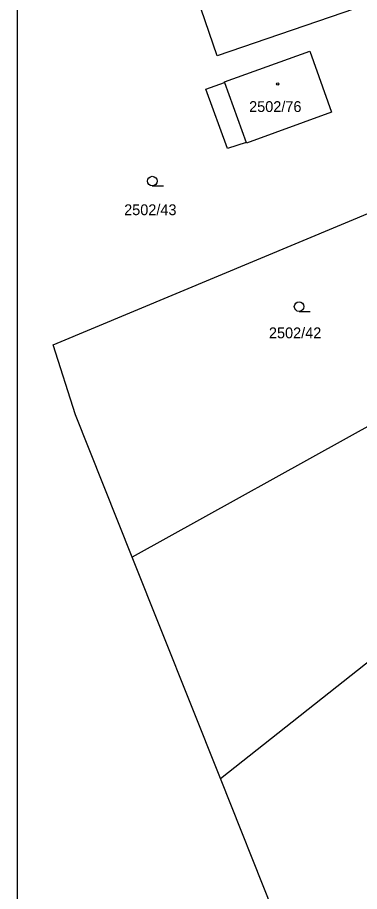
# Model space of a CAD drawing. Extents: x -558358 to -557517, y -1073786 to -1073189.
# Drawn here: x -558357.5 to -558303.9, y -1073559.5 to -1073422.1 of the extents above; entities that cross this region are included whole.
import ezdxf

# ---------------------------------------------------------------- set-up
doc = ezdxf.new("R2010")
doc.units = 0
for name, color, linetype in [('Hranice parcel', 7, 'Continuous'), ('Parcelní čísla', 7, 'Continuous'), ('Vnitřní kresba', 7, 'Continuous'), ('Vrstva 1', 7, 'Continuous'), ('Značky budov', 7, 'Continuous'), ('Značky kultur', 7, 'Continuous')]:
    doc.layers.add(name, color=color, linetype=linetype)

msp = doc.modelspace()

# ---------------------------------------------------------------- linework, layer by layer
at = {"layer": 'Hranice parcel'}
for p, q in [((-558326.19, -1073428.15), (-558335.97, -1073399.79)), ((-558291.74, -1073416.28), (-558326.19, -1073428.15)), ((-558351.92, -1073473.58), (-558280.07, -1073443.5)), ((-558269.87, -1073468.15), (-558339.52, -1073506.95)), ((-558325.69, -1073541.72), (-558259.89, -1073489.61)), ((-558325.69, -1073541.72), (-558339.52, -1073506.95)), ((-558314.35, -1073570.26), (-558325.69, -1073541.72))]:
    msp.add_line(p, q, dxfattribs=at)
for points in [[(-558321.61, -1073441.85), (-558321.65, -1073441.75), (-558324.57, -1073442.7), (-558327.97, -1073433.39), (-558325.04, -1073432.33), (-558325.07, -1073432.22), (-558311.66, -1073427.42), (-558308.26, -1073436.97), (-558321.61, -1073441.85)], [(-558339.52, -1073506.95), (-558348.44, -1073484.55), (-558351.92, -1073473.58)]]:
    msp.add_lwpolyline(points, dxfattribs=at)
at = {"layer": 'Vnitřní kresba'}
msp.add_line((-558325.04, -1073432.33), (-558321.65, -1073441.75), dxfattribs=at)
at = {"layer": 'Vrstva 1'}
msp.add_line((-558357.53, -1073784.09), (-558357.53, -1073190.09), dxfattribs=at)
at = {"layer": 'Značky budov'}
msp.add_circle((-558316.7, -1073432.55), 0.175, dxfattribs=at)
at = {"layer": 'Značky kultur'}
for p, q in [((-558336.38, -1073448.57), (-558334.63, -1073448.57)), ((-558313.35, -1073468.3), (-558311.6, -1073468.3))]:
    msp.add_line(p, q, dxfattribs=at)
for centre in [(-558336.38, -1073447.82), (-558313.35, -1073467.55)]:
    msp.add_circle(centre, 0.75, dxfattribs=at)

# ---------------------------------------------------------------- texts
at = {"layer": 'Parcelní čísla'}
for s, p in [('2502/76', (-558321.19, -1073436.96)), ('2502/43', (-558340.8, -1073453.18)), ('2502/42', (-558318.08, -1073472.53))]:
    msp.add_text(s, height=1.7, dxfattribs=at).set_placement(p)

doc.saveas('drawing.dxf')
